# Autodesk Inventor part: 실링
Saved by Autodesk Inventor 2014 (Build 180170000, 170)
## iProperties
Created: 2026-09
Part Number: 실링
Material: 일반
Document SubType Name: Modeling
Designer: dg
Density: 1 g/cm^3
Appearance: 기본값
Author: dg
Author: jhkim
Creation Date: 2026-08-26
Sending System: Autodesk Inventor 2027
Preprocessor: ST-DEVELOPER v20.1
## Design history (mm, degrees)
node "실링1"
node "솔리드3"
node "기준1"
